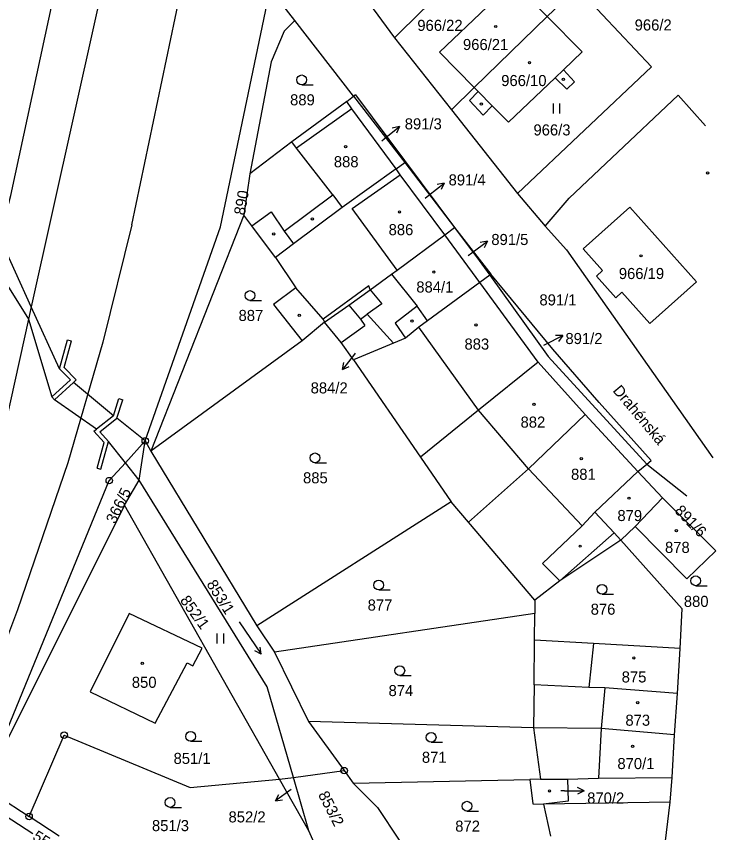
# Model space of a CAD drawing. Extents: x -776701 to -776081, y -974398 to -973771.
# Drawn here: x -776188.7 to -776081.4, y -974074.3 to -973949 of the extents above; entities that cross this region are included whole.
import ezdxf

# ---------------------------------------------------------------- set-up
doc = ezdxf.new("R2010")
doc.units = 0
for name, color, linetype in [('Hranice parcel', 7, 'Continuous'), ('Parcelní čísla', 7, 'Continuous'), ('Pop  PČ popisy', 7, 'Continuous'), ('Poz předměty', 7, 'Continuous'), ('Vnitřní kresba', 7, 'Continuous'), ('Značky bodu BP', 7, 'Continuous'), ('Značky budov', 7, 'Continuous'), ('Značky kultur', 7, 'Continuous')]:
    doc.layers.add(name, color=color, linetype=linetype)

msp = doc.modelspace()

# ---------------------------------------------------------------- linework, layer by layer
at = {"layer": 'Hranice parcel'}
for p, q in [((-776189.59, -973976.54), (-776179.58, -973929.94)), ((-776145.99, -973949.66), (-776149.78, -973944.77)), ((-776136.26, -973944.7), (-776130.7, -973952.3)), ((-776102.68, -973944.59), (-776107.23, -973949.03)), ((-776102.68, -973944.59), (-776091.19, -973956.75)), ((-776107.23, -973949.03), (-776118.42, -973959.96)), ((-776136.96, -973961.25), (-776145.99, -973949.66)), ((-776130.7, -973952.3), (-776121.93, -973963.39)), ((-776091.19, -973956.75), (-776111.8, -973976.22)), ((-776118.42, -973959.96), (-776121.93, -973963.39)), ((-776138, -973962.1), (-776136.96, -973961.25)), ((-776136.96, -973961.25), (-776129.11, -973971.44)), ((-776097.3, -973970.74), (-776087.12, -973961.13)), ((-776082.92, -973965.84), (-776087.12, -973961.13)), ((-776121.93, -973963.39), (-776111.8, -973976.22)), ((-776130.42, -973972.41), (-776129.11, -973971.44)), ((-776129.11, -973971.44), (-776121.45, -973981.44)), ((-776152.87, -973973.18), (-776153.8, -973979.55)), ((-776111.8, -973976.22), (-776107.56, -973981.25)), ((-776153.8, -973979.55), (-776168.07, -974015.77)), ((-776122.96, -973982.56), (-776121.45, -973981.44)), ((-776121.45, -973981.44), (-776115.88, -973988.61)), ((-776117.59, -973989.89), (-776122.96, -973982.56)), ((-776194.09, -973984.05), (-776186.87, -973995.48)), ((-776116.06, -973988.75), (-776117.59, -973989.89)), ((-776115.88, -973988.61), (-776116.06, -973988.75)), ((-776108.62, -974002.09), (-776117.59, -973989.89)), ((-776186.46, -973993.62), (-776186.87, -973995.48)), ((-776141.42, -973995.98), (-776137.69, -973993.34)), ((-776137.69, -973993.34), (-776135.91, -973995.5)), ((-776141.42, -973995.98), (-776144.84, -973998.83)), ((-776144.84, -973998.83), (-776168.07, -974015.77)), ((-776130.82, -973999.16), (-776136.99, -974001.76)), ((-776136.99, -974001.76), (-776126.7, -974016.67)), ((-776101.42, -974010.12), (-776108.62, -974002.09)), ((-776093.3, -974018.87), (-776101.42, -974010.12)), ((-776171.99, -974017.55), (-776168.94, -974014.19)), ((-776169.88, -974020.23), (-776168.94, -974014.19)), ((-776168.94, -974014.19), (-776168.07, -974015.77)), ((-776168.07, -974015.77), (-776151.82, -974042.59)), ((-776126.7, -974016.67), (-776121.97, -974023.54)), ((-776089.54, -974022.91), (-776093.3, -974018.87)), ((-776172.13, -974024.06), (-776169.88, -974020.23)), ((-776089.54, -974022.91), (-776093.73, -974027.35)), ((-776081.36, -974031.08), (-776089.54, -974022.91)), ((-776172.13, -974024.06), (-776193.76, -974067.27)), ((-776148.31, -974066.12), (-776172.13, -974024.06)), ((-776121.97, -974023.54), (-776151.82, -974042.59)), ((-776119.31, -974026.66), (-776121.97, -974023.54)), ((-776109.12, -974038.61), (-776119.31, -974026.66)), ((-776095.9, -974029.4), (-776093.73, -974027.35)), ((-776086.53, -974039.94), (-776095.9, -974029.4)), ((-776109.12, -974038.61), (-776109.14, -974040.66)), ((-776086.8, -974046.07), (-776086.53, -974039.94)), ((-776109.14, -974040.66), (-776149.12, -974046.61)), ((-776109.18, -974044.78), (-776109.14, -974040.66)), ((-776151.82, -974042.59), (-776149.12, -974046.61)), ((-776109.25, -974051.62), (-776109.18, -974044.78)), ((-776149.12, -974046.61), (-776143.9, -974057.28)), ((-776087.23, -974052.97), (-776086.8, -974046.07)), ((-776109.25, -974051.62), (-776109.32, -974058.22)), ((-776087.67, -974059.31), (-776087.23, -974052.97)), ((-776109.32, -974058.22), (-776143.9, -974057.28)), ((-776143.9, -974057.28), (-776138.41, -974064.8)), ((-776109.32, -974058.22), (-776108.28, -974066.12)), ((-776146.2, -974065.84), (-776138.41, -974064.8)), ((-776138.41, -974064.8), (-776137.02, -974066.7)), ((-776148.31, -974066.12), (-776146.2, -974065.84)), ((-776143.81, -974074.06), (-776148.31, -974066.12)), ((-776143.81, -974074.06), (-776146.2, -974065.84)), ((-776137.02, -974066.7), (-776109.88, -974066.15)), ((-776108.28, -974066.12), (-776109.88, -974066.15)), ((-776193.76, -974067.27), (-776186.79, -974071.85)), ((-776194.77, -974068.92), (-776186.22, -974074.45)), ((-776088.36, -974069.64), (-776107.78, -974069.96)), ((-776107.78, -974069.96), (-776106.71, -974074.86)), ((-776182.18, -974074.88), (-776186.79, -974071.85)), ((-776143.01, -974075.9), (-776143.81, -974074.06))]:
    msp.add_line(p, q, dxfattribs=at)
for points in [[(-776167.74, -973928.46), (-776173.47, -973935.17), (-776186.46, -973993.62)], [(-776130.7, -973952.3), (-776126.49, -973948.15), (-776111.76, -973934.97)], [(-776107.23, -973949.03), (-776112.46, -973943.72), (-776115.35, -973946.49), (-776116.81, -973945.05), (-776117.87, -973946.03), (-776116.47, -973947.55), (-776123.77, -973954.53), (-776118.42, -973959.96)], [(-776168.94, -974014.19), (-776157.37, -973981.34), (-776149.78, -973944.77)], [(-776107.23, -973949.03), (-776101.87, -973954.48), (-776104.75, -973957.23), (-776103.06, -973959.05), (-776104.22, -973960.21), (-776106.02, -973958.45), (-776113.17, -973965.28), (-776115.67, -973962.75), (-776117.06, -973964.17), (-776119.17, -973961.92), (-776117.83, -973960.56), (-776118.42, -973959.96)], [(-776145.99, -973949.66), (-776147.61, -973951.3), (-776149.59, -973956), (-776152.87, -973973.18)], [(-776138, -973962.1), (-776146.44, -973968.3), (-776152.87, -973973.18)], [(-776130.42, -973972.41), (-776137.25, -973963.2), (-776138, -973962.1)], [(-776107.56, -973981.25), (-776103.85, -973976.92), (-776097.3, -973970.74)], [(-776130.42, -973972.41), (-776138.73, -973978.35), (-776146.16, -973983.93), (-776148.95, -973986.03)], [(-776122.96, -973982.56), (-776129.81, -973973.34), (-776130.42, -973972.41)], [(-776186.46, -973993.62), (-776191.35, -973982.98), (-776189.59, -973976.54)], [(-776095.76, -973991.37), (-776096.7, -973992.2), (-776099.67, -973988.88), (-776098.73, -973988.05), (-776101.7, -973984.72), (-776094.53, -973978.32), (-776084.33, -973989.75), (-776091.49, -973996.15), (-776095.76, -973991.37)], [(-776148.95, -973986.03), (-776152.6, -973981.15), (-776153.8, -973979.55)], [(-776107.56, -973981.25), (-776104.28, -973984.85), (-776081.8, -974016.78)], [(-776137.69, -973993.34), (-776134.4, -973991), (-776131.15, -973988.6), (-776130.25, -973988), (-776122.96, -973982.56)], [(-776148.95, -973986.03), (-776145.82, -973990.7), (-776149.23, -973993.27), (-776144.84, -973998.83)], [(-776091.25, -974017.2), (-776099.26, -974008.29), (-776106.34, -974000.13), (-776115.88, -973988.61)], [(-776117.59, -973989.89), (-776125.6, -973995.78), (-776126.92, -973996.73), (-776129, -973998.4), (-776130.82, -973999.16)], [(-776186.87, -973995.48), (-776195.9, -974036.12), (-776202.98, -974064.31), (-776215.3, -974064.46)], [(-776135.91, -973995.5), (-776134.85, -973994.75), (-776130.82, -973999.16)], [(-776136.99, -974001.76), (-776138.84, -973999.06), (-776141.42, -973995.98)], [(-776108.62, -974002.09), (-776117.78, -974009.48), (-776126.7, -974016.67)], [(-776101.42, -974010.12), (-776110.09, -974018.45), (-776119.31, -974026.66)], [(-776193.76, -974067.27), (-776174.47, -974020.28), (-776171.99, -974017.55)], [(-776093.3, -974018.87), (-776091.91, -974017.74), (-776091.25, -974017.2)], [(-776093.3, -974018.87), (-776099.9, -974025.1), (-776096.95, -974028.3), (-776095.9, -974029.4)], [(-776146.2, -974065.84), (-776150.23, -974051.95), (-776169.88, -974020.23)], [(-776093.73, -974027.35), (-776085.8, -974035.35), (-776081.36, -974031.08)], [(-776095.9, -974029.4), (-776105.28, -974035.69), (-776109.12, -974038.61)], [(-776171.44, -974040.68), (-776177.4, -974052.7), (-776167.44, -974057.5), (-776162.53, -974048.25), (-776161.63, -974048.7), (-776160.2, -974046), (-776171.44, -974040.68)], [(-776086.8, -974046.07), (-776100.12, -974045.3), (-776109.18, -974044.78)], [(-776087.23, -974052.97), (-776098.4, -974052.1), (-776100.85, -974052.03), (-776109.25, -974051.62)], [(-776186.79, -974071.85), (-776181.39, -974059.36), (-776162.03, -974067.4), (-776148.31, -974066.12)], [(-776087.67, -974059.31), (-776098.95, -974058.35), (-776109.32, -974058.22)], [(-776088.36, -974069.64), (-776088.04, -974065.84), (-776087.67, -974059.31)], [(-776137.02, -974066.7), (-776133.27, -974070.47), (-776126.62, -974080.51)], [(-776109.88, -974066.15), (-776109.43, -974069.89), (-776107.78, -974069.96)], [(-776108.28, -974066.12), (-776104.12, -974066.1), (-776103.99, -974069.47), (-776107.78, -974069.96)], [(-776089.3, -974081.68), (-776089.29, -974077.28), (-776088.36, -974069.64)]]:
    msp.add_lwpolyline(points, dxfattribs=at)
at = {"layer": 'Pop  PČ popisy'}
for p, q in [((-776132.26, -973967.82), (-776129.93, -973965.93)), ((-776129.93, -973965.93), (-776131.02, -973966.17)), ((-776129.93, -973965.93), (-776130.39, -973966.95)), ((-776132.61, -973968.11), (-776132.26, -973967.82)), ((-776125.41, -973976.46), (-776123.05, -973974.61)), ((-776123.05, -973974.61), (-776124.14, -973974.83)), ((-776123.05, -973974.61), (-776123.53, -973975.62)), ((-776125.99, -973976.91), (-776125.41, -973976.46)), ((-776118.82, -973985.33), (-776116.42, -973983.52)), ((-776116.42, -973983.52), (-776117.52, -973983.73)), ((-776116.42, -973983.52), (-776116.92, -973984.53)), ((-776119.37, -973985.75), (-776118.82, -973985.33)), ((-776107.52, -973999.38), (-776104.85, -973998.02)), ((-776104.85, -973998.02), (-776105.97, -973998.03)), ((-776104.85, -973998.02), (-776105.51, -973998.92)), ((-776107.77, -973999.51), (-776107.52, -973999.38)), ((-776136.81, -974000.87), (-776138.66, -974003.23)), ((-776136.69, -974000.72), (-776136.81, -974000.87)), ((-776138.66, -974003.23), (-776138.44, -974002.14)), ((-776138.66, -974003.23), (-776137.65, -974002.75)), ((-776146.54, -974067.68), (-776148.97, -974069.44)), ((-776104.56, -974067.9), (-776105.12, -974067.9)), ((-776104.56, -974067.9), (-776101.56, -974067.9)), ((-776101.56, -974067.9), (-776102.56, -974067.4)), ((-776101.56, -974067.9), (-776102.56, -974068.4)), ((-776148.97, -974069.44), (-776148.45, -974068.45)), ((-776148.97, -974069.44), (-776147.86, -974069.26))]:
    msp.add_line(p, q, dxfattribs=at)
at = {"layer": 'Poz předměty'}
for p, q in [((-776170.99, -973981), (-776163.09, -973943.22)), ((-776170.99, -973981), (-776175.48, -973999.05)), ((-776175.48, -973999.05), (-776180.85, -974017.57)), ((-776180.85, -974017.57), (-776188.57, -974040.14)), ((-776188.57, -974040.14), (-776193.46, -974053.03))]:
    msp.add_line(p, q, dxfattribs=at)
at = {"layer": 'Vnitřní kresba'}
for p, q in [((-776106.02, -973958.45), (-776104.75, -973957.23)), ((-776136.65, -973961.05), (-776136.96, -973961.25)), ((-776136.65, -973961.05), (-776121.45, -973981.44)), ((-776117.83, -973960.56), (-776115.67, -973962.75)), ((-776137.25, -973963.2), (-776145.71, -973969.26)), ((-776145.71, -973969.26), (-776146.44, -973968.3)), ((-776140.13, -973976.39), (-776145.71, -973969.26)), ((-776137.17, -973978.5), (-776129.81, -973973.34)), ((-776147.6, -973982.01), (-776140.13, -973976.39)), ((-776140.13, -973976.39), (-776138.73, -973978.35)), ((-776152.6, -973981.15), (-776149.6, -973979)), ((-776149.6, -973979), (-776147.6, -973982.01)), ((-776130.25, -973988), (-776137.17, -973978.5)), ((-776121.45, -973981.44), (-776117.69, -973986.48)), ((-776147.6, -973982.01), (-776146.16, -973983.93)), ((-776117.69, -973986.48), (-776116.06, -973988.75)), ((-776131.15, -973988.6), (-776127.2, -973993.5)), ((-776116.06, -973988.75), (-776107.08, -974001.25)), ((-776134.6, -973990.4), (-776141.61, -973995.5)), ((-776134.4, -973991), (-776134.6, -973990.4)), ((-776141.61, -973995.5), (-776145.82, -973990.7)), ((-776134.4, -973991), (-776132.61, -973993.15)), ((-776182.09, -974003.11), (-776186.46, -973993.62)), ((-776132.61, -973993.15), (-776134.85, -973994.75)), ((-776127.2, -973993.5), (-776130.55, -973996.11)), ((-776125.6, -973995.78), (-776127.2, -973993.5)), ((-776186.87, -973995.48), (-776183.28, -974007.42)), ((-776141.61, -973995.5), (-776141.42, -973995.98)), ((-776135.91, -973995.5), (-776135.21, -973996.48)), ((-776138.84, -973999.06), (-776135.21, -973996.48)), ((-776130.55, -973996.11), (-776129, -973998.4)), ((-776117.78, -974009.48), (-776126.92, -973996.73)), ((-776182.09, -974003.11), (-776180.87, -973998.66)), ((-776181.42, -974002.94), (-776180.29, -973998.82)), ((-776180.87, -973998.66), (-776180.29, -973998.82)), ((-776091.91, -974017.74), (-776107.08, -974001.25)), ((-776179.57, -974004.83), (-776181.42, -974002.94)), ((-776182.09, -974003.11), (-776180.43, -974004.81)), ((-776180.43, -974004.81), (-776183.28, -974007.42)), ((-776182.87, -974007.86), (-776179.96, -974005.2)), ((-776179.96, -974005.2), (-776179.57, -974004.83)), ((-776173.81, -974010.32), (-776179.96, -974005.2)), ((-776183.28, -974007.42), (-776182.87, -974007.86)), ((-776176.44, -974012.41), (-776182.87, -974007.86)), ((-776173.81, -974010.32), (-776172.98, -974007.68)), ((-776173.29, -974010.68), (-776172.41, -974007.86)), ((-776172.98, -974007.68), (-776172.41, -974007.86)), ((-776173.81, -974010.32), (-776176.44, -974012.41)), ((-776110.09, -974018.45), (-776117.78, -974009.48)), ((-776175.94, -974012.78), (-776173.29, -974010.68)), ((-776168.94, -974014.19), (-776173.29, -974010.68)), ((-776176.82, -974012.71), (-776176.44, -974012.41)), ((-776176.82, -974012.71), (-776175.24, -974014.44)), ((-776174.57, -974014.28), (-776175.94, -974012.78)), ((-776175.76, -974018.52), (-776174.57, -974014.28)), ((-776171.99, -974017.55), (-776174.57, -974014.28)), ((-776176.34, -974018.36), (-776175.24, -974014.44)), ((-776169.88, -974020.23), (-776171.99, -974017.55)), ((-776091.91, -974017.74), (-776085.79, -974022.61)), ((-776176.34, -974018.36), (-776175.76, -974018.52)), ((-776110.09, -974018.45), (-776101.85, -974027.2)), ((-776101.85, -974027.2), (-776099.9, -974025.1)), ((-776107.95, -974033), (-776101.85, -974027.2)), ((-776096.95, -974028.3), (-776105.28, -974035.69)), ((-776105.28, -974035.69), (-776107.95, -974033)), ((-776100.12, -974045.3), (-776100.85, -974052.03)), ((-776098.4, -974052.1), (-776098.95, -974058.35)), ((-776098.95, -974058.35), (-776099.35, -974065.94)), ((-776104.12, -974066.1), (-776099.35, -974065.94)), ((-776099.35, -974065.94), (-776088.04, -974065.84))]:
    msp.add_line(p, q, dxfattribs=at)
at = {"layer": 'Značky bodu BP'}
for centre, radius in [((-776168.94, -974014.19), 0.5), ((-776168.94, -974014.19), 0.0303), ((-776174.47, -974020.28), 0.5), ((-776174.47, -974020.28), 0.0303), ((-776181.39, -974059.36), 0.5), ((-776181.39, -974059.36), 0.0303), ((-776138.41, -974064.8), 0.5), ((-776138.41, -974064.8), 0.0303), ((-776186.79, -974071.85), 0.5), ((-776186.79, -974071.85), 0.0303)]:
    msp.add_circle(centre, radius, dxfattribs=at)
at = {"layer": 'Značky budov'}
for centre in [(-776115.13, -973950.58), (-776109.95, -973956.11), (-776104.74, -973958.7), (-776117.34, -973962.49), (-776138.19, -973969.02), (-776082.6, -973973.05), (-776129.91, -973979.04), (-776143.28, -973980.12), (-776149.22, -973982.41), (-776092.82, -973985.78), (-776124.64, -973988.27), (-776145.29, -973994.92), (-776128, -973995.8), (-776118.17, -973996.38), (-776109.27, -974008.57), (-776102, -974016.9), (-776094.67, -974022.98), (-776087.38, -974027.97), (-776102.17, -974030.34), (-776169.4, -974048.32), (-776093.93, -974047.5), (-776093.32, -974054.35), (-776094.11, -974061.09), (-776106.88, -974067.92)]:
    msp.add_circle(centre, 0.175, dxfattribs=at)
at = {"layer": 'Značky kultur'}
for p, q in [((-776144.92, -973959.52), (-776143.17, -973959.52)), ((-776106.27, -973963.92), (-776106.27, -973962.42)), ((-776105.27, -973963.92), (-776105.27, -973962.42)), ((-776152.87, -973992.62), (-776151.12, -973992.62)), ((-776142.89, -974017.54), (-776141.14, -974017.54)), ((-776084.43, -974036.41), (-776082.68, -974036.41)), ((-776133.1, -974037.07), (-776131.35, -974037.07)), ((-776098.81, -974037.71), (-776097.06, -974037.71)), ((-776154.52, -974041.96), (-776151.16, -974046.94)), ((-776157.9, -974045.27), (-776157.9, -974043.77)), ((-776156.9, -974045.27), (-776156.9, -974043.77)), ((-776151.16, -974046.94), (-776152.12, -974046.41)), ((-776151.16, -974046.94), (-776151.29, -974045.85)), ((-776129.86, -974050.2), (-776128.11, -974050.2)), ((-776161.99, -974060.3), (-776160.24, -974060.3)), ((-776125.05, -974060.44), (-776123.3, -974060.44)), ((-776165.13, -974070.44), (-776163.38, -974070.44)), ((-776119.55, -974071.01), (-776117.8, -974071.01))]:
    msp.add_line(p, q, dxfattribs=at)
for centre in [(-776144.92, -973958.77), (-776152.87, -973991.87), (-776142.89, -974016.79), (-776133.1, -974036.32), (-776084.43, -974035.66), (-776098.81, -974036.96), (-776129.86, -974049.45), (-776161.99, -974059.55), (-776125.05, -974059.69), (-776165.13, -974069.69), (-776119.55, -974070.26)]:
    msp.add_circle(centre, 0.75, dxfattribs=at)

# ---------------------------------------------------------------- texts
at = {"layer": 'Parcelní čísla'}
for s, p in [('966/22', (-776127.17, -973951.25)), ('966/2', (-776093.8, -973951.19)), ('966/21', (-776120.16, -973954.19)), ('966/10', (-776114.29, -973959.72)), ('889', (-776146.71, -973962.68)), ('891/3', (-776129.1, -973966.37)), ('966/3', (-776109.34, -973967.3)), ('888', (-776139.99, -973972.18)), ('891/4', (-776122.37, -973974.97)), ('886', (-776131.58, -973982.61)), ('891/5', (-776115.81, -973984.12)), ('966/19', (-776096.23, -973989.34)), ('884/1', (-776127.33, -973991.41)), ('891/1', (-776108.42, -973993.39)), ('887', (-776154.62, -973995.78)), ('891/2', (-776104.43, -973999.32)), ('883', (-776119.93, -974000.17)), ('884/2', (-776143.55, -974006.9)), ('882', (-776111.32, -974012.15)), ('885', (-776144.72, -974020.7)), ('881', (-776103.57, -974020.16)), ('879', (-776096.45, -974026.49)), ('878', (-776089.14, -974031.38)), ('880', (-776086.25, -974039.67)), ('877', (-776134.8, -974040.23)), ('876', (-776100.55, -974040.87)), ('850', (-776171.01, -974052.09)), ('875', (-776095.79, -974051.27)), ('874', (-776131.59, -974053.36)), ('873', (-776095.22, -974057.91)), ('871', (-776126.47, -974063.6)), ('851/1', (-776164.6, -974063.77)), ('870/1', (-776096.45, -974064.56)), ('870/2', (-776101.09, -974069.85)), ('852/2', (-776156.16, -974072.75)), ('851/3', (-776167.92, -974074.09)), ('872', (-776121.35, -974074.17))]:
    msp.add_text(s, height=1.7, dxfattribs=at).set_placement(p)
for s, rotation, p in [('890', 80, (-776153.67, -973979.63)), ('366/5', 64, (-776173.55, -974027.03)), ('891/6', 314, (-776087.77, -974025.02)), ('853/1', 302, (-776159.6, -974036.16)), ('852/1', 306, (-776163.69, -974038.68)), ('853/2', 297, (-776142.45, -974068.47)), ('550/4', 327, (-776186.39, -974075.29))]:
    msp.add_text(s, height=1.7, rotation=rotation, dxfattribs=at).set_placement(p)
at = {"layer": 'Pop  PČ popisy'}
msp.add_text('Drahénská', height=1.7, rotation=310, dxfattribs=at).set_placement((-776097.25, -974006.51))

doc.saveas('drawing.dxf')
